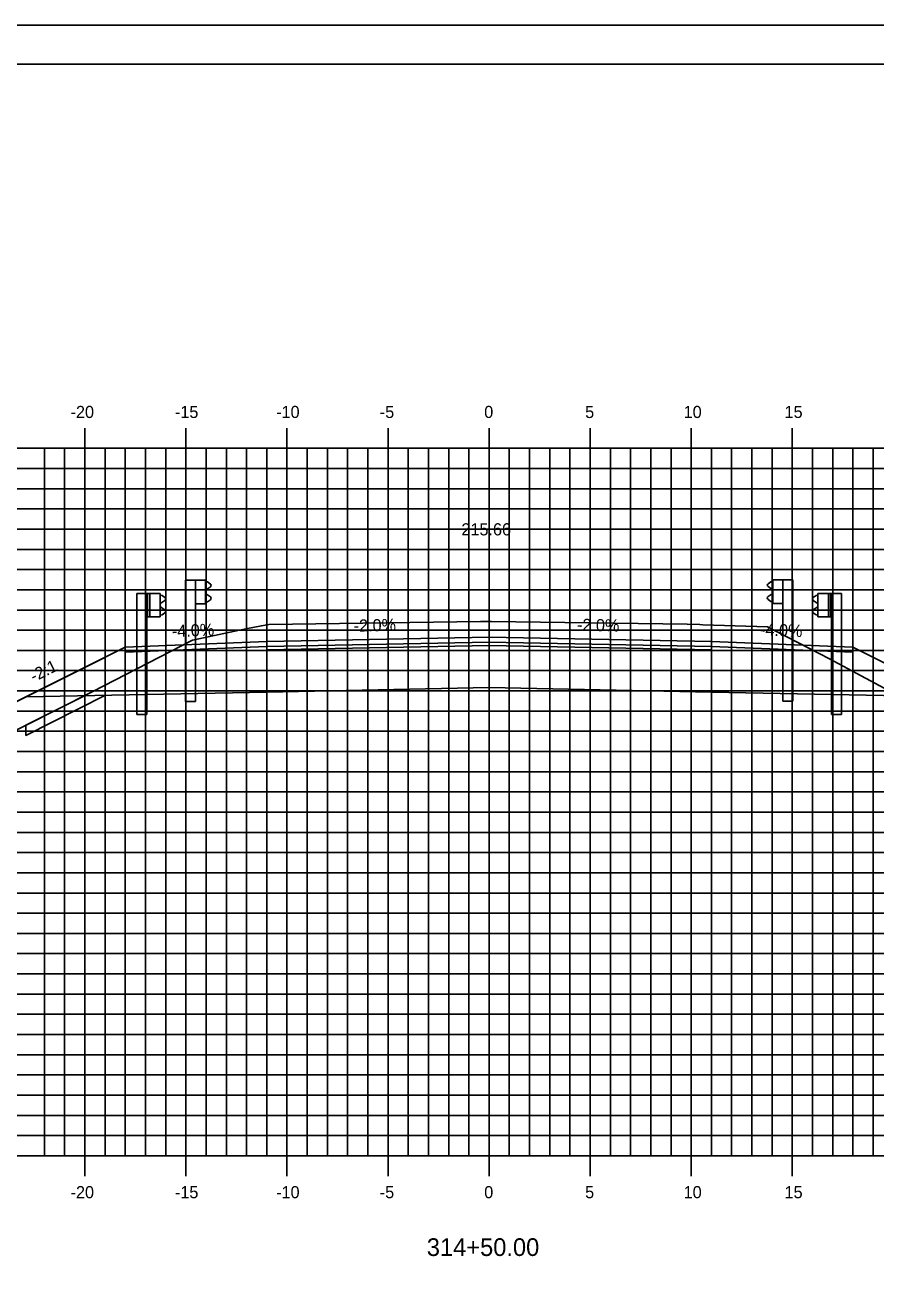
# Model space of a CAD drawing. Extents: x 1138320 to 1138490, y 608981 to 609091.
# Drawn here: x 1138379.7 to 1138421.8, y 609029.3 to 609091.3 of the extents above; entities that cross this region are included whole.
import ezdxf

# ---------------------------------------------------------------- set-up
doc = ezdxf.new("R2010")
doc.units = 0
for name, color, linetype in [('ANNOTATION', 7, 'Continuous'), ('BORDER', 7, 'Continuous'), ('D_Guardrail_Beam_Lt', 7, 'Continuous'), ('D_Guardrail_Beam_Rt', 7, 'Continuous'), ('D_Roadway_Centerline', 7, 'Continuous'), ('D_Roadway_Centerline_Text', 7, 'Continuous'), ('D_Roadway_Edge_Shoulder', 7, 'Continuous'), ('D_Roadway_Edge_TW', 7, 'Continuous'), ('D_Roadway_Pavement', 7, 'Continuous'), ('D_Roadway_SlopeLines', 7, 'Continuous'), ('D_Roadway_SubGrade', 7, 'Continuous'), ('H_V ANNOTATION', 7, 'Continuous'), ('MAJOR', 7, 'Continuous'), ('MINOR', 7, 'Continuous'), ('PLOT BOUNDARY', 7, 'Continuous'), ('S_Guardrail_Beam', 7, 'Continuous'), ('S_Roadway_Centerline', 7, 'Continuous'), ('SHADING', 7, 'Continuous')]:
    doc.layers.add(name, color=color, linetype=linetype)

msp = doc.modelspace()

# ---------------------------------------------------------------- linework, layer by layer
msp.add_lwpolyline([(1138347.192, 609041.753), (1138377.761, 609057.037), (1138379.761, 609058.037), (1138384.678, 609060.496), (1138384.679, 609060.496), (1138391.679, 609060.776), (1138402.679, 609060.996), (1138413.679, 609060.776), (1138420.679, 609060.496), (1138425.596, 609058.037), (1138427.596, 609057.037), (1138456.106, 609042.782)])
at = {"layer": 'BORDER'}
msp.add_lwpolyline([(1138327.679, 608984.335), (1138487.679, 608984.335), (1138487.679, 609089.335), (1138327.679, 609089.335)], close=True, dxfattribs=at)
at = {"layer": 'D_Guardrail_Beam_Lt'}
for p, q in [((1138385.25, 609063.159), (1138385.25, 609057.159)), ((1138385.721, 609063.159), (1138385.25, 609063.159)), ((1138386.408, 609063.159), (1138385.721, 609063.159)), ((1138385.721, 609063.159), (1138385.721, 609061.992)), ((1138385.783, 609063.159), (1138385.783, 609061.992)), ((1138385.887, 609063.159), (1138385.887, 609061.992)), ((1138386.408, 609061.992), (1138386.408, 609063.159)), ((1138386.408, 609063.076), (1138386.482, 609063.061)), ((1138386.642, 609062.811), (1138386.446, 609062.675)), ((1138386.498, 609063.054), (1138386.642, 609062.954)), ((1138418.86, 609063.054), (1138418.716, 609062.954)), ((1138418.716, 609062.811), (1138418.912, 609062.675)), ((1138418.95, 609063.076), (1138418.876, 609063.061)), ((1138386.413, 609062.611), (1138386.413, 609062.541)), ((1138386.446, 609062.476), (1138386.642, 609062.34)), ((1138386.642, 609062.197), (1138386.498, 609062.097)), ((1138418.912, 609062.476), (1138418.716, 609062.34)), ((1138418.716, 609062.197), (1138418.86, 609062.097)), ((1138418.945, 609062.611), (1138418.945, 609062.541)), ((1138385.721, 609061.992), (1138386.408, 609061.992)), ((1138385.742, 609057.159), (1138385.742, 609061.992)), ((1138386.482, 609062.09), (1138386.408, 609062.076)), ((1138418.876, 609062.09), (1138418.95, 609062.076)), ((1138385.742, 609057.159), (1138385.25, 609057.159))]:
    msp.add_line(p, q, dxfattribs=at)
for centre, major_axis, start_param, end_param in [((1138386.474, 609063.02), (0.0417, 0), 0.959931, 1.376053), ((1138386.591, 609062.883), (0.0877, 0), 5.323254, 7.243116), ((1138418.767, 609062.883), (-0.0877, 0), 5.323254, 7.243116), ((1138418.884, 609063.02), (-0.0417, 0), 4.907132, 5.323254), ((1138386.492, 609062.611), (-0.0789, 0), 5.323254, 6.283185), ((1138386.492, 609062.541), (-0.0789, 0), 6.283185, 7.243116), ((1138386.591, 609062.268), (0.0877, 0), 5.323254, 7.243116), ((1138418.767, 609062.268), (-0.0877, 0), 5.323254, 7.243116), ((1138418.867, 609062.611), (0.0789, 0), 0, 0.959931), ((1138418.867, 609062.541), (0.0789, 0), 5.323254, 6.283185), ((1138386.474, 609062.131), (0.0417, 0), 4.907132, 5.323254), ((1138418.884, 609062.131), (-0.0417, 0), 0.959931, 1.376053)]:
    msp.add_ellipse(centre, major_axis=major_axis, ratio=0.995501, start_param=start_param, end_param=end_param, dxfattribs=at)
at = {"layer": 'D_Guardrail_Beam_Rt'}
for p, q in [((1138418.95, 609063.159), (1138419.637, 609063.159)), ((1138418.95, 609061.992), (1138418.95, 609063.159)), ((1138419.471, 609063.159), (1138419.471, 609061.992)), ((1138419.575, 609063.159), (1138419.575, 609061.992)), ((1138419.637, 609063.159), (1138420.108, 609063.159)), ((1138419.637, 609063.159), (1138419.637, 609061.992)), ((1138420.108, 609063.159), (1138420.108, 609057.159)), ((1138419.637, 609061.992), (1138418.95, 609061.992)), ((1138419.617, 609057.159), (1138419.617, 609061.992)), ((1138419.617, 609057.159), (1138420.108, 609057.159))]:
    msp.add_line(p, q, dxfattribs=at)
at = {"layer": 'D_Roadway_Edge_Shoulder'}
for points in [[(1138391.679, 609060.776), (1138384.679, 609060.496), (1138384.679, 609060.246), (1138391.679, 609060.526)], [(1138413.679, 609060.776), (1138420.679, 609060.496), (1138420.679, 609060.246), (1138413.679, 609060.526)]]:
    msp.add_lwpolyline(points, close=True, dxfattribs=at)
at = {"layer": 'D_Roadway_Edge_TW'}
msp.add_lwpolyline([(1138391.679, 609060.526), (1138391.679, 609060.776), (1138402.679, 609060.996), (1138413.679, 609060.776), (1138413.679, 609060.526), (1138402.679, 609060.746)], close=True, dxfattribs=at)
at = {"layer": 'D_Roadway_Pavement'}
msp.add_lwpolyline([(1138391.679, 609060.359), (1138391.679, 609060.526), (1138402.679, 609060.746), (1138413.679, 609060.526), (1138413.679, 609060.359), (1138402.679, 609060.579)], close=True, dxfattribs=at)
at = {"layer": 'D_Roadway_SlopeLines'}
for points in [[(1138384.018, 609058.789), (1138384.018, 609058.789)], [(1138379.761, 609058.037), (1138377.761, 609057.037)], [(1138379.761, 609056.633), (1138379.761, 609056.133), (1138383.694, 609058.116)]]:
    msp.add_lwpolyline(points, dxfattribs=at)
at = {"layer": 'D_Roadway_SubGrade'}
msp.add_lwpolyline([(1138384.679, 609060.496), (1138382.679, 609059.496), (1138347.193, 609041.753)], dxfattribs=at)
for points in [[(1138391.679, 609060.359), (1138391.679, 609060.526), (1138384.679, 609060.246), (1138384.679, 609060.496), (1138384.678, 609060.496), (1138379.761, 609058.037), (1138391.679, 609058.276)], [(1138391.679, 609058.276), (1138391.679, 609060.359), (1138402.679, 609060.579), (1138413.679, 609060.359), (1138413.679, 609058.276), (1138402.679, 609058.496)], [(1138413.679, 609060.359), (1138413.679, 609060.526), (1138420.679, 609060.246), (1138420.679, 609060.496), (1138420.679, 609060.496), (1138425.596, 609058.037), (1138413.679, 609058.276)]]:
    msp.add_lwpolyline(points, close=True, dxfattribs=at)
at = {"layer": 'MAJOR'}
for p, q in [((1138382.679, 609071.337), (1138382.679, 609070.335)), ((1138387.679, 609071.337), (1138387.679, 609070.335)), ((1138392.679, 609071.337), (1138392.679, 609070.335)), ((1138397.679, 609071.337), (1138397.679, 609070.335)), ((1138402.679, 609071.337), (1138402.679, 609070.335)), ((1138407.679, 609071.337), (1138407.679, 609070.335)), ((1138412.679, 609071.337), (1138412.679, 609070.335)), ((1138417.679, 609071.337), (1138417.679, 609070.335)), ((1138332.679, 609070.335), (1138472.679, 609070.335)), ((1138332.679, 609070.335), (1138472.679, 609070.335)), ((1138382.679, 609035.335), (1138382.679, 609070.335)), ((1138387.679, 609035.335), (1138387.679, 609070.335)), ((1138392.679, 609035.335), (1138392.679, 609070.335)), ((1138397.679, 609035.335), (1138397.679, 609070.335)), ((1138402.679, 609035.335), (1138402.679, 609070.335)), ((1138407.679, 609035.335), (1138407.679, 609070.335)), ((1138412.679, 609035.335), (1138412.679, 609070.335)), ((1138417.679, 609035.335), (1138417.679, 609070.335)), ((1138332.679, 609065.335), (1138472.679, 609065.335)), ((1138332.679, 609060.335), (1138472.679, 609060.335)), ((1138332.679, 609055.335), (1138472.679, 609055.335)), ((1138332.679, 609050.335), (1138472.679, 609050.335)), ((1138332.679, 609045.335), (1138472.679, 609045.335)), ((1138332.679, 609040.335), (1138472.679, 609040.335)), ((1138332.679, 609035.335), (1138472.679, 609035.335)), ((1138332.679, 609035.335), (1138472.679, 609035.335)), ((1138382.679, 609034.333), (1138382.679, 609035.335)), ((1138387.679, 609034.333), (1138387.679, 609035.335)), ((1138392.679, 609034.333), (1138392.679, 609035.335)), ((1138397.679, 609034.333), (1138397.679, 609035.335)), ((1138402.679, 609034.333), (1138402.679, 609035.335)), ((1138407.679, 609034.333), (1138407.679, 609035.335)), ((1138412.679, 609034.333), (1138412.679, 609035.335)), ((1138417.679, 609034.333), (1138417.679, 609035.335))]:
    msp.add_line(p, q, dxfattribs=at)
at = {"layer": 'MINOR'}
for p, q in [((1138380.679, 609035.335), (1138380.679, 609070.335)), ((1138381.679, 609035.335), (1138381.679, 609070.335)), ((1138383.679, 609035.335), (1138383.679, 609070.335)), ((1138384.679, 609035.335), (1138384.679, 609070.335)), ((1138385.679, 609035.335), (1138385.679, 609070.335)), ((1138386.679, 609035.335), (1138386.679, 609070.335)), ((1138388.679, 609035.335), (1138388.679, 609070.335)), ((1138389.679, 609035.335), (1138389.679, 609070.335)), ((1138390.679, 609035.335), (1138390.679, 609070.335)), ((1138391.679, 609035.335), (1138391.679, 609070.335)), ((1138393.679, 609035.335), (1138393.679, 609070.335)), ((1138394.679, 609035.335), (1138394.679, 609070.335)), ((1138395.679, 609035.335), (1138395.679, 609070.335)), ((1138396.679, 609035.335), (1138396.679, 609070.335)), ((1138398.679, 609035.335), (1138398.679, 609070.335)), ((1138399.679, 609035.335), (1138399.679, 609070.335)), ((1138400.679, 609035.335), (1138400.679, 609070.335)), ((1138401.679, 609035.335), (1138401.679, 609070.335)), ((1138403.679, 609035.335), (1138403.679, 609070.335)), ((1138404.679, 609035.335), (1138404.679, 609070.335)), ((1138405.679, 609035.335), (1138405.679, 609070.335)), ((1138406.679, 609035.335), (1138406.679, 609070.335)), ((1138408.679, 609035.335), (1138408.679, 609070.335)), ((1138409.679, 609035.335), (1138409.679, 609070.335)), ((1138410.679, 609035.335), (1138410.679, 609070.335)), ((1138411.679, 609035.335), (1138411.679, 609070.335)), ((1138413.679, 609035.335), (1138413.679, 609070.335)), ((1138414.679, 609035.335), (1138414.679, 609070.335)), ((1138415.679, 609035.335), (1138415.679, 609070.335)), ((1138416.679, 609035.335), (1138416.679, 609070.335)), ((1138418.679, 609035.335), (1138418.679, 609070.335)), ((1138419.679, 609035.335), (1138419.679, 609070.335)), ((1138420.679, 609035.335), (1138420.679, 609070.335)), ((1138421.679, 609035.335), (1138421.679, 609070.335)), ((1138332.679, 609069.335), (1138472.679, 609069.335)), ((1138332.679, 609068.335), (1138472.679, 609068.335)), ((1138332.679, 609067.335), (1138472.679, 609067.335)), ((1138332.679, 609066.335), (1138472.679, 609066.335)), ((1138332.679, 609064.335), (1138472.679, 609064.335)), ((1138332.679, 609063.335), (1138472.679, 609063.335)), ((1138332.679, 609062.335), (1138472.679, 609062.335)), ((1138332.679, 609061.335), (1138472.679, 609061.335)), ((1138332.679, 609059.335), (1138472.679, 609059.335)), ((1138332.679, 609058.335), (1138472.679, 609058.335)), ((1138332.679, 609057.335), (1138472.679, 609057.335)), ((1138332.679, 609056.335), (1138472.679, 609056.335)), ((1138332.679, 609054.335), (1138472.679, 609054.335)), ((1138332.679, 609053.335), (1138472.679, 609053.335)), ((1138332.679, 609052.335), (1138472.679, 609052.335)), ((1138332.679, 609051.335), (1138472.679, 609051.335)), ((1138332.679, 609049.335), (1138472.679, 609049.335)), ((1138332.679, 609048.335), (1138472.679, 609048.335)), ((1138332.679, 609047.335), (1138472.679, 609047.335)), ((1138332.679, 609046.335), (1138472.679, 609046.335)), ((1138332.679, 609044.335), (1138472.679, 609044.335)), ((1138332.679, 609043.335), (1138472.679, 609043.335)), ((1138332.679, 609042.335), (1138472.679, 609042.335)), ((1138332.679, 609041.335), (1138472.679, 609041.335)), ((1138332.679, 609039.335), (1138472.679, 609039.335)), ((1138332.679, 609038.335), (1138472.679, 609038.335)), ((1138332.679, 609037.335), (1138472.679, 609037.335)), ((1138332.679, 609036.335), (1138472.679, 609036.335))]:
    msp.add_line(p, q, dxfattribs=at)
at = {"layer": 'PLOT BOUNDARY'}
msp.add_lwpolyline([(1138319.586, 608981.276), (1138489.586, 608981.276), (1138489.586, 609091.276), (1138319.586, 609091.276)], close=True, dxfattribs=at)
at = {"layer": 'S_Guardrail_Beam'}
for p, q in [((1138387.666, 609063.816), (1138387.666, 609057.816)), ((1138388.157, 609063.816), (1138387.666, 609063.816)), ((1138388.647, 609063.816), (1138388.157, 609063.816)), ((1138388.157, 609063.816), (1138388.157, 609062.649)), ((1138388.647, 609062.649), (1138388.647, 609063.816)), ((1138388.647, 609063.743), (1138388.729, 609063.729)), ((1138388.889, 609063.479), (1138388.694, 609063.343)), ((1138388.746, 609063.722), (1138388.889, 609063.622)), ((1138416.623, 609063.737), (1138416.48, 609063.637)), ((1138416.48, 609063.494), (1138416.675, 609063.358)), ((1138416.722, 609063.758), (1138416.64, 609063.744)), ((1138416.722, 609063.831), (1138417.211, 609063.831)), ((1138416.722, 609062.664), (1138416.722, 609063.831)), ((1138417.211, 609063.831), (1138417.703, 609063.831)), ((1138417.211, 609063.831), (1138417.211, 609062.664)), ((1138417.703, 609063.831), (1138417.703, 609057.831)), ((1138388.66, 609063.278), (1138388.66, 609063.187)), ((1138388.694, 609063.123), (1138388.889, 609062.987)), ((1138388.889, 609062.844), (1138388.746, 609062.744)), ((1138416.675, 609063.138), (1138416.48, 609063.002)), ((1138416.48, 609062.859), (1138416.623, 609062.759)), ((1138416.709, 609063.293), (1138416.709, 609063.202)), ((1138388.157, 609057.816), (1138388.157, 609062.649)), ((1138388.157, 609062.649), (1138388.647, 609062.649)), ((1138388.729, 609062.737), (1138388.647, 609062.722)), ((1138416.64, 609062.752), (1138416.722, 609062.737)), ((1138417.211, 609062.664), (1138416.722, 609062.664)), ((1138417.211, 609057.831), (1138417.211, 609062.664)), ((1138388.157, 609057.816), (1138387.666, 609057.816)), ((1138417.211, 609057.831), (1138417.703, 609057.831))]:
    msp.add_line(p, q, dxfattribs=at)
for centre, major_axis, start_param, end_param in [((1138388.722, 609063.688), (0.0417, 0), 0.959931, 1.396263), ((1138388.839, 609063.55), (0.0877, 0), 5.323254, 7.243116), ((1138416.53, 609063.565), (-0.0877, 0), 5.323254, 7.243116), ((1138416.647, 609063.703), (-0.0417, 0), 4.886922, 5.323254), ((1138388.739, 609063.278), (-0.0789, 0), 5.323254, 6.283185), ((1138388.739, 609063.187), (-0.0789, 0), 6.283185, 7.243116), ((1138388.839, 609062.915), (0.0877, 0), 5.323254, 7.243116), ((1138416.53, 609062.93), (-0.0877, 0), 5.323254, 7.243116), ((1138416.63, 609063.293), (0.0789, 0), 0, 0.959931), ((1138416.63, 609063.202), (0.0789, 0), 5.323254, 6.283185), ((1138388.722, 609062.778), (0.0417, 0), 4.886922, 5.323254), ((1138416.647, 609062.793), (-0.0417, 0), 0.959931, 1.396263)]:
    msp.add_ellipse(centre, major_axis=major_axis, ratio=0.995501, start_param=start_param, end_param=end_param, dxfattribs=at)
at = {"layer": 'S_Roadway_Centerline'}
msp.add_lwpolyline([(1138332.679, 609041.616), (1138336.049, 609041.666), (1138348.96, 609041.767), (1138358.116, 609046.004), (1138359.488, 609046.419), (1138362.571, 609047.965), (1138383.071, 609058.302), (1138388, 609060.837), (1138390.649, 609061.402), (1138391.414, 609061.554), (1138391.787, 609061.616), (1138402.249, 609061.759), (1138402.804, 609061.769), (1138412.483, 609061.629), (1138413.106, 609061.62), (1138413.261, 609061.6), (1138416.451, 609061.498), (1138419.518, 609059.918), (1138450.838, 609043.119), (1138450.903, 609043.108), (1138451.517, 609042.958), (1138472.679, 609042.149)], dxfattribs=at)
at = {"layer": 'SHADING'}
for p, q in [((1138382.661, 609058.095), (1138379.761, 609056.633)), ((1138383.694, 609058.116), (1138382.661, 609058.095))]:
    msp.add_line(p, q, dxfattribs=at)
msp.add_lwpolyline([(1138379.761, 609056.633), (1138379.761, 609056.133), (1138383.694, 609058.116)], dxfattribs=at)

# ---------------------------------------------------------------- texts
at = {"layer": 'ANNOTATION'}
for s, rotation, p in [('-4.0%', 2.29061, (1138386.995, 609060.989)), ('-2.0%', 1.14576, (1138395.982, 609061.262)), ('-2.0%', 358.85424, (1138407.022, 609061.309)), ('-4.0%', 357.70939, (1138416.075, 609061.081)), ('-2:1', 26.56505, (1138380.149, 609058.749))]:
    msp.add_text(s, height=0.6, rotation=rotation, dxfattribs=at).set_placement(p)
at = {"layer": 'D_Roadway_Centerline'}
for s, p in [('C', (1138402.674, 609060.996)), ('L', (1138402.679, 609060.988))]:
    msp.add_text(s, height=0.0146, dxfattribs=at).set_placement(p)
at = {"layer": 'D_Roadway_Centerline_Text'}
msp.add_text('215.66', height=0.6, dxfattribs=at).set_placement((1138401.309, 609066.028))
at = {"layer": 'H_V ANNOTATION'}
for s, height, p in [('-20', 0.6, (1138381.973, 609071.835)), ('-15', 0.6, (1138387.136, 609071.835)), ('-10', 0.6, (1138392.144, 609071.835)), ('-5', 0.6, (1138397.27, 609071.835)), ('0', 0.6, (1138402.438, 609071.835)), ('5', 0.6, (1138407.43, 609071.835)), ('10', 0.6, (1138412.304, 609071.835)), ('15', 0.6, (1138417.296, 609071.835)), ('-20', 0.6, (1138381.973, 609033.235)), ('-15', 0.6, (1138387.136, 609033.235)), ('-10', 0.6, (1138392.144, 609033.235)), ('-5', 0.6, (1138397.27, 609033.235)), ('0', 0.6, (1138402.438, 609033.235)), ('5', 0.6, (1138407.43, 609033.235)), ('10', 0.6, (1138412.304, 609033.235)), ('15', 0.6, (1138417.296, 609033.235)), ('314+50.00', 0.875, (1138399.597, 609030.378))]:
    msp.add_text(s, height=height, dxfattribs=at).set_placement(p)
at = {"layer": 'S_Roadway_Centerline'}
for s, p in [('C', (1138402.799, 609061.769)), ('L', (1138402.804, 609061.761))]:
    msp.add_text(s, height=0.0146, dxfattribs=at).set_placement(p)

doc.saveas('drawing.dxf')
